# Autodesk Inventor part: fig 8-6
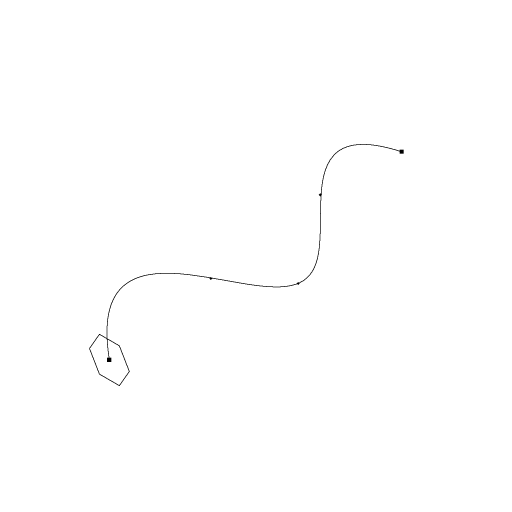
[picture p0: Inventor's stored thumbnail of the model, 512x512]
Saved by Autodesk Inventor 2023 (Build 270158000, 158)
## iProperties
Created: 2006-01
Part Number: fig 8-6
Document SubType Name: Modeling
Designer: CADCIM
Density: 1 g/cm^3
Material: Generic
Appearance: Default
Author: CADCIM
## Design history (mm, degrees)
sketch "Sketch1"
  geometry: 5 further points
  constraints: 5 other
sketch "Sketch2"
  geometry: L1 (-4.728, 0)-(-2.364, 4.094); L2 (-2.364, 4.094)-(2.364, 4.094); L3 (2.364, 4.094)-(4.728, 0); L4 (4.728, 0)-(2.364, -4.094); L5 (2.364, -4.094)-(-2.364, -4.094); L6 (-2.364, -4.094)-(-4.728, 0); 1 further point
  constraints: 12 end point, 13 other
body "Solid1"
